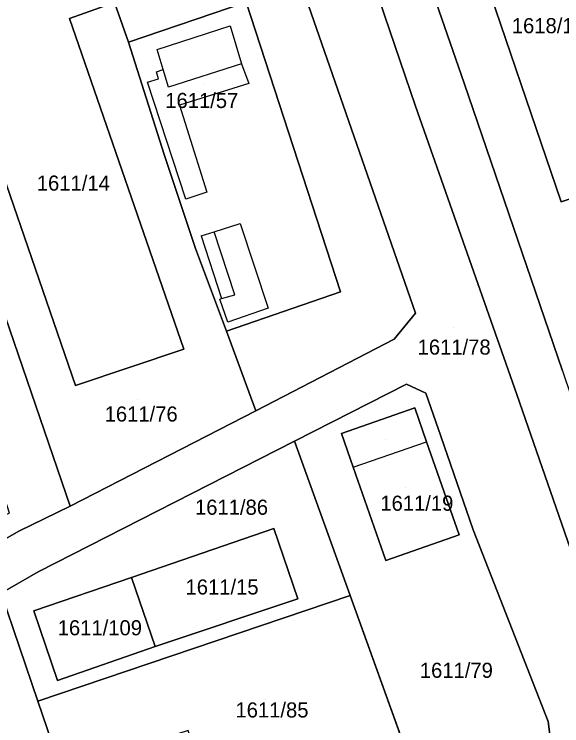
# Model space of a CAD drawing. Extents: x -263943 to -261149, y -1236934 to -1230686.
# Drawn here: x -262422.9 to -262350.4, y -1236325.7 to -1236231.5 of the extents above; entities that cross this region are included whole.
import ezdxf

# ---------------------------------------------------------------- set-up
doc = ezdxf.new("R2010")
doc.units = 0
for name, color, linetype in [('body_kn', 7, 'Continuous'), ('kladpar_druhypozemkov', 7, 'Continuous'), ('kladpar_hranice', 7, 'Continuous'), ('kladpar_parcelnecisla', 7, 'Continuous'), ('kladpar_plochy', 7, 'Continuous'), ('zappar_hrandruhpozemk', 7, 'Continuous')]:
    doc.layers.add(name, color=color, linetype=linetype)

msp = doc.modelspace()

# ---------------------------------------------------------------- linework, layer by layer
at = {"layer": 'body_kn'}
for p, q in [((-262415.55, -1236232.09), (-262415.55, -1236232.09)), ((-262394.3, -1236233.06), (-262394.3, -1236233.06)), ((-262407.77, -1236235.24), (-262407.77, -1236235.24)), ((-262407.77, -1236235.24), (-262407.77, -1236235.24)), ((-262403.96, -1236236.18), (-262403.96, -1236236.18)), ((-262403.96, -1236236.18), (-262403.96, -1236236.18)), ((-262392.78, -1236238.07), (-262392.78, -1236238.07)), ((-262404.05, -1236239.15), (-262404.05, -1236239.15)), ((-262403.15, -1236238.85), (-262403.15, -1236238.85)), ((-262403.79, -1236240.08), (-262403.79, -1236240.08)), ((-262405.23, -1236240.5), (-262405.23, -1236240.5)), ((-262402.44, -1236241.18), (-262402.44, -1236241.18)), ((-262391.85, -1236240.69), (-262391.85, -1236240.69)), ((-262363.32, -1236240.66), (-262363.32, -1236240.66)), ((-262401, -1236243.56), (-262401, -1236243.56)), ((-262369.76, -1236243.7), (-262369.76, -1236243.7)), ((-262403.04, -1236250.08), (-262403.04, -1236250.08)), ((-262397.38, -1236255.09), (-262397.38, -1236255.09)), ((-262400.17, -1236256.02), (-262400.17, -1236256.02)), ((-262350.51, -1236256.35), (-262350.51, -1236256.35)), ((-262392.98, -1236259.25), (-262392.98, -1236259.25)), ((-262398.15, -1236260.85), (-262398.15, -1236260.85)), ((-262396.43, -1236260.32), (-262396.43, -1236260.32)), ((-262398.91, -1236262.55), (-262398.91, -1236262.55)), ((-262398.91, -1236262.55), (-262398.91, -1236262.55)), ((-262379.7, -1236268.26), (-262379.7, -1236268.26)), ((-262395.67, -1236269.24), (-262395.67, -1236269.24)), ((-262395.46, -1236269.18), (-262395.46, -1236269.18)), ((-262393.67, -1236268.66), (-262393.67, -1236268.66)), ((-262389.27, -1236270.45), (-262389.27, -1236270.45)), ((-262369.79, -1236271.08), (-262369.79, -1236271.08)), ((-262394.61, -1236272.3), (-262394.61, -1236272.3)), ((-262394.78, -1236273.49), (-262394.78, -1236273.49)), ((-262372.59, -1236274.55), (-262372.59, -1236274.55)), ((-262372.59, -1236274.55), (-262372.59, -1236274.55)), ((-262400.45, -1236275.85), (-262400.45, -1236275.85)), ((-262400.45, -1236275.85), (-262400.45, -1236275.85)), ((-262414.77, -1236280.66), (-262414.77, -1236280.66)), ((-262370.94, -1236280.48), (-262370.94, -1236280.48)), ((-262368.39, -1236281.71), (-262368.39, -1236281.71)), ((-262356.34, -1236281.87), (-262356.34, -1236281.87)), ((-262390.89, -1236284.01), (-262390.89, -1236284.01)), ((-262369.87, -1236283.65), (-262369.87, -1236283.65)), ((-262379.55, -1236287.02), (-262379.55, -1236287.02)), ((-262366.43, -1236287.37), (-262366.43, -1236287.37)), ((-262385.79, -1236288.05), (-262385.79, -1236288.05)), ((-262368.31, -1236288.12), (-262368.31, -1236288.12)), ((-262378.02, -1236291.49), (-262378.02, -1236291.49)), ((-262378.02, -1236291.49), (-262378.02, -1236291.49)), ((-262415.47, -1236296.67), (-262415.47, -1236296.67)), ((-262388.53, -1236299.59), (-262388.53, -1236299.59)), ((-262388.53, -1236299.59), (-262388.53, -1236299.59)), ((-262422.25, -1236299.97), (-262422.25, -1236299.97)), ((-262363.98, -1236300.46), (-262363.98, -1236300.46)), ((-262363.98, -1236300.46), (-262363.98, -1236300.46)), ((-262362.14, -1236299.78), (-262362.14, -1236299.78)), ((-262373.71, -1236303.83), (-262373.71, -1236303.83)), ((-262419.7, -1236305.34), (-262419.7, -1236305.34)), ((-262407.37, -1236306.11), (-262407.37, -1236306.11)), ((-262385.36, -1236308.9), (-262385.36, -1236308.9)), ((-262378.43, -1236308.5), (-262378.43, -1236308.5)), ((-262420.28, -1236310.5), (-262420.28, -1236310.5)), ((-262404.24, -1236315.25), (-262404.24, -1236315.25)), ((-262404.24, -1236315.25), (-262404.24, -1236315.25)), ((-262417.14, -1236319.71), (-262417.14, -1236319.71)), ((-262419.77, -1236322.48), (-262419.77, -1236322.48)), ((-262419.77, -1236322.48), (-262419.77, -1236322.48)), ((-262352.22, -1236325.16), (-262352.22, -1236325.16))]:
    msp.add_line(p, q, dxfattribs=at)
at = {"layer": 'kladpar_druhypozemkov'}
for p, q in [((-262352.61, -1236232.18), (-262352.61, -1236232.18)), ((-262397.83, -1236240.8), (-262397.83, -1236240.8)), ((-262416.2, -1236252.66), (-262416.2, -1236252.66)), ((-262364.75, -1236273.04), (-262364.75, -1236273.04)), ((-262406.53, -1236282.55), (-262406.53, -1236282.55)), ((-262373.79, -1236287.89), (-262373.79, -1236287.89)), ((-262371.04, -1236294.24), (-262371.04, -1236294.24)), ((-262394, -1236295.81), (-262394, -1236295.81)), ((-262395.88, -1236306.2), (-262395.88, -1236306.2)), ((-262412.91, -1236311.77), (-262412.91, -1236311.77)), ((-262364.81, -1236317.17), (-262364.81, -1236317.17)), ((-262389.68, -1236322.23), (-262389.68, -1236322.23))]:
    msp.add_line(p, q, dxfattribs=at)
at = {"layer": 'kladpar_hranice'}
for points in [[(-262337.02, -1236337.39), (-262342.59, -1236321.56), (-262356.34, -1236281.87), (-262369.76, -1236243.7), (-262382.07, -1236207.49), (-262384.1, -1236201.72), (-262377.49, -1236199.53), (-262371.5, -1236217.09), (-262363.32, -1236240.66), (-262350.33, -1236278.74), (-262339.8, -1236309.86), (-262336.49, -1236319.02), (-262329.74, -1236338.53)], [(-262382.07, -1236207.49), (-262369.76, -1236243.7), (-262356.34, -1236281.87), (-262342.59, -1236321.56)], [(-262350.33, -1236278.74), (-262363.32, -1236240.66), (-262371.5, -1236217.09), (-262366.16, -1236215.48), (-262364.9, -1236219.14), (-262363.95, -1236218.82), (-262362.41, -1236223.24), (-262361.81, -1236223.04), (-262350.51, -1236256.35), (-262340.71, -1236253.03)], [(-262372.59, -1236274.55), (-262390.89, -1236284.01), (-262394.78, -1236273.49), (-262379.7, -1236268.26), (-262392.18, -1236229.93), (-262407.77, -1236235.24), (-262409.62, -1236229.96), (-262411, -1236226.04), (-262411.82, -1236223.71), (-262390.98, -1236216.71), (-262388.18, -1236218.16), (-262369.79, -1236271.08), (-262372.59, -1236274.55)], [(-262351.1, -1236333.79), (-262352.22, -1236325.16), (-262362.14, -1236299.78), (-262366.43, -1236287.37), (-262368.39, -1236281.71), (-262370.94, -1236280.48), (-262385.79, -1236288.05), (-262419.7, -1236305.34), (-262424.6, -1236308.15), (-262430.31, -1236311.48), (-262452.08, -1236323.98), (-262454.28, -1236318.22), (-262436.31, -1236307.99), (-262430.84, -1236304.87), (-262422.25, -1236299.97), (-262415.47, -1236296.67), (-262390.89, -1236284.01), (-262372.59, -1236274.55), (-262369.79, -1236271.08), (-262388.18, -1236218.16)], [(-262361.81, -1236223.04), (-262351.96, -1236219.69), (-262342.71, -1236247.11), (-262341.62, -1236246.74), (-262340.85, -1236249.02), (-262341.94, -1236249.39), (-262340.71, -1236253.03), (-262350.51, -1236256.35), (-262361.81, -1236223.04)], [(-262407.77, -1236235.24), (-262403.04, -1236250.08), (-262398.91, -1236262.55), (-262394.78, -1236273.49), (-262390.89, -1236284.01), (-262415.47, -1236296.67), (-262426.37, -1236264.93), (-262437.18, -1236233.46), (-262435.37, -1236231.55), (-262411.82, -1236223.71), (-262411, -1236226.04), (-262428.76, -1236231.9), (-262427.24, -1236236.14), (-262429.78, -1236237.15), (-262414.77, -1236280.66), (-262400.45, -1236275.85), (-262415.55, -1236232.09), (-262409.62, -1236229.96), (-262407.77, -1236235.24)], [(-262400.45, -1236275.85), (-262414.77, -1236280.66), (-262429.78, -1236237.15), (-262427.24, -1236236.14), (-262428.76, -1236231.9), (-262411, -1236226.04), (-262409.62, -1236229.96), (-262415.55, -1236232.09), (-262400.45, -1236275.85)], [(-262398.91, -1236262.55), (-262403.04, -1236250.08), (-262407.77, -1236235.24), (-262392.18, -1236229.93), (-262379.7, -1236268.26), (-262394.78, -1236273.49), (-262398.91, -1236262.55)], [(-262432.32, -1236300.37), (-262423.51, -1236297.59), (-262424.83, -1236293.51), (-262428.94, -1236280.79), (-262431.27, -1236273.59), (-262440.52, -1236276.66), (-262442.53, -1236270.1), (-262426.37, -1236264.93), (-262415.47, -1236296.67), (-262422.25, -1236299.97), (-262430.84, -1236304.87), (-262432.32, -1236300.37)], [(-262385.79, -1236288.05), (-262370.94, -1236280.48), (-262368.39, -1236281.71), (-262366.43, -1236287.37), (-262362.14, -1236299.78), (-262352.22, -1236325.16), (-262351.1, -1236333.79), (-262368.47, -1236336.17)], [(-262379.55, -1236287.02), (-262378.02, -1236291.49), (-262373.71, -1236303.83), (-262363.98, -1236300.46), (-262368.31, -1236288.12), (-262369.87, -1236283.65), (-262379.55, -1236287.02)], [(-262363.98, -1236300.46), (-262373.71, -1236303.83), (-262378.02, -1236291.49), (-262379.55, -1236287.02), (-262369.87, -1236283.65), (-262368.31, -1236288.12), (-262363.98, -1236300.46)], [(-262419.77, -1236322.48), (-262424.6, -1236308.15), (-262419.7, -1236305.34), (-262385.79, -1236288.05)], [(-262385.79, -1236288.05), (-262378.43, -1236308.5), (-262419.77, -1236322.48)], [(-262368.47, -1236336.17), (-262371.33, -1236328.21), (-262378.43, -1236308.5), (-262385.79, -1236288.05)], [(-262388.53, -1236299.59), (-262407.37, -1236306.11), (-262420.28, -1236310.5), (-262417.14, -1236319.71), (-262404.24, -1236315.25), (-262385.36, -1236308.9), (-262388.53, -1236299.59)], [(-262388.53, -1236299.59), (-262385.36, -1236308.9), (-262404.24, -1236315.25), (-262407.37, -1236306.11), (-262388.53, -1236299.59)], [(-262404.24, -1236315.25), (-262417.14, -1236319.71), (-262420.28, -1236310.5), (-262407.37, -1236306.11), (-262404.24, -1236315.25)], [(-262402.01, -1236363.74), (-262411.5, -1236366.94), (-262415.63, -1236354.56), (-262430.31, -1236311.48), (-262424.6, -1236308.15), (-262419.77, -1236322.48), (-262413.07, -1236342.11), (-262407.59, -1236358.31), (-262404.15, -1236357.51), (-262402.01, -1236363.74)], [(-262396.45, -1236336.59), (-262399.84, -1236326.37), (-262412.97, -1236330.58), (-262409.56, -1236340.94), (-262413.07, -1236342.11), (-262419.77, -1236322.48), (-262378.43, -1236308.5), (-262371.33, -1236328.21), (-262387.91, -1236333.76), (-262396.45, -1236336.59)]]:
    msp.add_lwpolyline(points, dxfattribs=at)
at = {"layer": 'kladpar_plochy'}
for p, q in [((-262363.32, -1236240.66), (-262371.5, -1236217.09)), ((-262361.81, -1236223.04), (-262350.51, -1236256.35)), ((-262350.33, -1236278.74), (-262363.32, -1236240.66)), ((-262350.51, -1236256.35), (-262340.71, -1236253.03)), ((-262385.79, -1236288.05), (-262370.94, -1236280.48)), ((-262370.94, -1236280.48), (-262368.39, -1236281.71)), ((-262368.39, -1236281.71), (-262366.43, -1236287.37)), ((-262369.87, -1236283.65), (-262379.55, -1236287.02)), ((-262368.31, -1236288.12), (-262369.87, -1236283.65)), ((-262379.55, -1236287.02), (-262378.02, -1236291.49)), ((-262366.43, -1236287.37), (-262362.14, -1236299.78)), ((-262419.7, -1236305.34), (-262385.79, -1236288.05)), ((-262385.79, -1236288.05), (-262378.43, -1236308.5)), ((-262378.43, -1236308.5), (-262385.79, -1236288.05)), ((-262363.98, -1236300.46), (-262368.31, -1236288.12)), ((-262378.02, -1236291.49), (-262373.71, -1236303.83)), ((-262388.53, -1236299.59), (-262407.37, -1236306.11)), ((-262385.36, -1236308.9), (-262388.53, -1236299.59)), ((-262373.71, -1236303.83), (-262363.98, -1236300.46)), ((-262362.14, -1236299.78), (-262352.22, -1236325.16)), ((-262424.6, -1236308.15), (-262419.7, -1236305.34)), ((-262407.37, -1236306.11), (-262420.28, -1236310.5)), ((-262419.77, -1236322.48), (-262424.6, -1236308.15)), ((-262378.43, -1236308.5), (-262419.77, -1236322.48)), ((-262404.24, -1236315.25), (-262385.36, -1236308.9)), ((-262371.33, -1236328.21), (-262378.43, -1236308.5)), ((-262420.28, -1236310.5), (-262417.14, -1236319.71)), ((-262417.14, -1236319.71), (-262404.24, -1236315.25)), ((-262352.22, -1236325.16), (-262351.1, -1236333.79))]:
    msp.add_line(p, q, dxfattribs=at)
for points in [[(-262337.02, -1236337.39), (-262342.59, -1236321.56), (-262356.34, -1236281.87), (-262369.76, -1236243.7), (-262382.07, -1236207.49), (-262384.1, -1236201.72), (-262377.49, -1236199.53), (-262371.5, -1236217.09), (-262363.32, -1236240.66), (-262350.33, -1236278.74), (-262339.8, -1236309.86), (-262336.49, -1236319.02), (-262329.74, -1236338.53)], [(-262382.07, -1236207.49), (-262369.76, -1236243.7), (-262356.34, -1236281.87), (-262342.59, -1236321.56)], [(-262351.1, -1236333.79), (-262352.22, -1236325.16), (-262362.14, -1236299.78), (-262366.43, -1236287.37), (-262368.39, -1236281.71), (-262370.94, -1236280.48), (-262385.79, -1236288.05), (-262419.7, -1236305.34), (-262424.6, -1236308.15), (-262430.31, -1236311.48), (-262452.08, -1236323.98), (-262454.28, -1236318.22), (-262436.31, -1236307.99), (-262430.84, -1236304.87), (-262422.25, -1236299.97), (-262415.47, -1236296.67), (-262390.89, -1236284.01), (-262372.59, -1236274.55), (-262369.79, -1236271.08), (-262388.18, -1236218.16)]]:
    msp.add_lwpolyline(points, dxfattribs=at)
for points in [[(-262372.59, -1236274.55), (-262390.89, -1236284.01), (-262394.78, -1236273.49), (-262379.7, -1236268.26), (-262392.18, -1236229.93), (-262407.77, -1236235.24), (-262409.62, -1236229.96), (-262411, -1236226.04), (-262411.82, -1236223.71), (-262390.98, -1236216.71), (-262388.18, -1236218.16), (-262369.79, -1236271.08)], [(-262361.81, -1236223.04), (-262351.96, -1236219.69), (-262342.71, -1236247.11), (-262341.62, -1236246.74), (-262340.85, -1236249.02), (-262341.94, -1236249.39), (-262340.71, -1236253.03), (-262350.51, -1236256.35)], [(-262407.77, -1236235.24), (-262403.04, -1236250.08), (-262398.91, -1236262.55), (-262394.78, -1236273.49), (-262390.89, -1236284.01), (-262415.47, -1236296.67), (-262426.37, -1236264.93), (-262437.18, -1236233.46), (-262435.37, -1236231.55), (-262411.82, -1236223.71), (-262411, -1236226.04), (-262428.76, -1236231.9), (-262427.24, -1236236.14), (-262429.78, -1236237.15), (-262414.77, -1236280.66), (-262400.45, -1236275.85), (-262415.55, -1236232.09), (-262409.62, -1236229.96)], [(-262400.45, -1236275.85), (-262414.77, -1236280.66), (-262429.78, -1236237.15), (-262427.24, -1236236.14), (-262428.76, -1236231.9), (-262411, -1236226.04), (-262409.62, -1236229.96), (-262415.55, -1236232.09)], [(-262398.91, -1236262.55), (-262403.04, -1236250.08), (-262407.77, -1236235.24), (-262392.18, -1236229.93), (-262379.7, -1236268.26), (-262394.78, -1236273.49)], [(-262432.32, -1236300.37), (-262423.51, -1236297.59), (-262424.83, -1236293.51), (-262428.94, -1236280.79), (-262431.27, -1236273.59), (-262440.52, -1236276.66), (-262442.53, -1236270.1), (-262426.37, -1236264.93), (-262415.47, -1236296.67), (-262422.25, -1236299.97), (-262430.84, -1236304.87)], [(-262363.98, -1236300.46), (-262373.71, -1236303.83), (-262378.02, -1236291.49), (-262379.55, -1236287.02), (-262369.87, -1236283.65), (-262368.31, -1236288.12)], [(-262388.53, -1236299.59), (-262385.36, -1236308.9), (-262404.24, -1236315.25), (-262407.37, -1236306.11)], [(-262404.24, -1236315.25), (-262417.14, -1236319.71), (-262420.28, -1236310.5), (-262407.37, -1236306.11)], [(-262402.01, -1236363.74), (-262411.5, -1236366.94), (-262415.63, -1236354.56), (-262430.31, -1236311.48), (-262424.6, -1236308.15), (-262419.77, -1236322.48), (-262413.07, -1236342.11), (-262407.59, -1236358.31), (-262404.15, -1236357.51)], [(-262396.45, -1236336.59), (-262399.84, -1236326.37), (-262412.97, -1236330.58), (-262409.56, -1236340.94), (-262413.07, -1236342.11), (-262419.77, -1236322.48), (-262378.43, -1236308.5), (-262371.33, -1236328.21), (-262387.91, -1236333.76)]]:
    msp.add_lwpolyline(points, close=True, dxfattribs=at)
at = {"layer": 'zappar_hrandruhpozemk'}
for p, q in [((-262392.78, -1236238.07), (-262402.44, -1236241.18)), ((-262392.78, -1236238.07), (-262391.85, -1236240.69)), ((-262391.85, -1236240.69), (-262401, -1236243.56)), ((-262392.98, -1236259.25), (-262389.27, -1236270.45)), ((-262398.15, -1236260.85), (-262395.46, -1236269.18)), ((-262393.67, -1236268.66), (-262396.43, -1236260.32)), ((-262378.02, -1236291.49), (-262368.31, -1236288.12))]:
    msp.add_line(p, q, dxfattribs=at)
for points in [[(-262403.96, -1236236.18), (-262394.3, -1236233.06), (-262392.78, -1236238.07)], [(-262402.44, -1236241.18), (-262403.15, -1236238.85), (-262403.96, -1236236.18)], [(-262401, -1236243.56), (-262397.38, -1236255.09), (-262400.17, -1236256.02), (-262405.23, -1236240.5), (-262403.79, -1236240.08), (-262404.05, -1236239.15), (-262403.15, -1236238.85)], [(-262398.15, -1236260.85), (-262396.43, -1236260.32), (-262392.98, -1236259.25)], [(-262389.27, -1236270.45), (-262394.61, -1236272.3), (-262395.67, -1236269.24), (-262395.46, -1236269.18), (-262393.67, -1236268.66)]]:
    msp.add_lwpolyline(points, dxfattribs=at)

# ---------------------------------------------------------------- texts
at = {"layer": 'kladpar_parcelnecisla'}
for s, p in [('1618/12', (-262357.021, -1236234.04)), ('1611/57', (-262402.89, -1236243.94)), ('1611/14', (-262419.893, -1236254.88)), ('1611/78', (-262369.489, -1236276.59)), ('1611/76', (-262410.915, -1236285.45)), ('1611/86', (-262398.954, -1236297.79)), ('1611/19', (-262374.423, -1236297.26)), ('1611/15', (-262400.208, -1236308.35)), ('1611/109', (-262417.125, -1236313.75)), ('1611/79', (-262369.195, -1236319.38)), ('1611/85', (-262393.599, -1236324.63))]:
    msp.add_text(s, height=2, dxfattribs=at).set_placement(p)

doc.saveas('drawing.dxf')
